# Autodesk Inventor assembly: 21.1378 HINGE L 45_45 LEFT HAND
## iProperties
Created: 2007-01
Part Number: 21.1378 HINGE L 45_45 LEFT HAND
Document SubType Name: Assembly
Designer: Andy Moles
Author: Andy Moles
